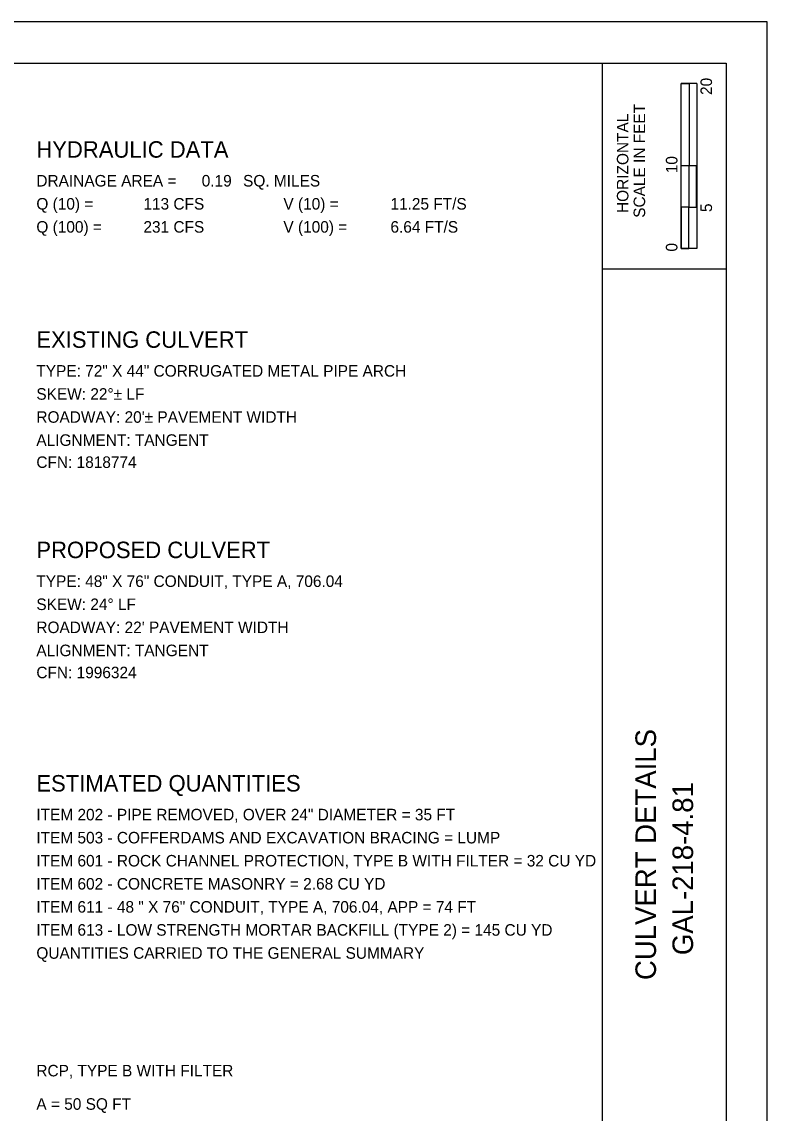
# Model space of a CAD drawing. Extents: x 0 to 2700, y -8 to 220.
# Drawn here: x 249.5 to 340, y 87.5 to 220 of the extents above; entities that cross this region are included whole.
import ezdxf

# ---------------------------------------------------------------- set-up
doc = ezdxf.new("R2010")
doc.units = 0
for name, color, linetype in [('DR_X_Culvert', 7, 'Continuous'), ('MT_P_Work_Area', 7, 'Continuous'), ('PF_X_Ground_Line', 7, 'Continuous'), ('XS_X_Pavt', 7, 'Continuous')]:
    doc.layers.add(name, color=color, linetype=linetype)

msp = doc.modelspace()

# ---------------------------------------------------------------- linework, layer by layer
at = {"layer": 'DR_X_Culvert'}
for p, q in [((329.57, 192.5), (329.57, 212.5)), ((331.44, 212.5), (329.57, 212.5)), ((329.57, 202.5), (329.57, 212.5)), ((329.57, 212.5), (330.5, 212.5)), ((330.5, 212.5), (330.51, 212.5)), ((330.51, 212.5), (330.51, 202.5)), ((331.44, 212.5), (331.44, 192.5)), ((330.51, 202.5), (329.57, 202.5)), ((331.43, 202.5), (330.5, 202.5)), ((330.5, 202.5), (330.5, 197.5)), ((331.43, 197.5), (331.43, 202.5)), ((330.5, 197.5), (329.57, 197.5)), ((329.57, 197.5), (329.57, 192.5)), ((330.5, 192.5), (330.5, 197.5)), ((330.5, 197.5), (331.43, 197.5)), ((331.44, 192.5), (329.57, 192.5)), ((329.57, 192.5), (330.5, 192.5))]:
    msp.add_line(p, q, dxfattribs=at)
at = {"layer": 'PF_X_Ground_Line'}
msp.add_lwpolyline([(0, 0), (340, 0), (340, 220), (0, 220)], close=True, dxfattribs=at)
at = {"layer": 'XS_X_Pavt'}
for p, q in [((320, 5), (320, 215)), ((320, 190), (335, 190))]:
    msp.add_line(p, q, dxfattribs=at)
msp.add_lwpolyline([(15, 215), (335, 215), (335, 5), (15, 5)], close=True, dxfattribs=at)

# ---------------------------------------------------------------- texts
at = {"layer": 'DR_X_Culvert'}
for s, height, p in [('20', 1.4, (333.3, 211.12)), ('SCALE IN FEET', 1.4, (325.18, 196.21)), ('HORIZONTAL', 1.4, (323.15, 196.79)), ('10', 1.4, (329.1, 201.62)), ('5', 1.4, (333.3, 196.91)), ('0', 1.4, (329.1, 192.11)), ('CULVERT DETAILS', 2.5, (326.5, 103.69)), ('GAL-218-4.81', 2.5, (331, 106.71))]:
    msp.add_text(s, height=height, rotation=90, dxfattribs=at).set_placement(p)
for s, height, p in [('HYDRAULIC DATA', 2, (251.25, 203.51)), ('DRAINAGE AREA =', 1.4, (251.25, 200.01)), ('0.19', 1.4, (271.33, 200.01)), ('SQ. MILES', 1.4, (276.35, 200.01)), ('Q (10) =', 1.4, (251.25, 197.21)), ('113 CFS', 1.4, (264.25, 197.21)), ('V (10) =', 1.4, (281.25, 197.21)), ('11.25 FT/S', 1.4, (294.25, 197.21)), ('Q (100) =', 1.4, (251.25, 194.41)), ('231 CFS', 1.4, (264.25, 194.41)), ('V (100) =', 1.4, (281.25, 194.41)), ('6.64 FT/S', 1.4, (294.25, 194.41)), ('EXISTING CULVERT', 2, (251.25, 180.43)), ('TYPE: 72" X 44" CORRUGATED METAL PIPE ARCH', 1.4, (251.25, 176.93)), ('SKEW: 22°± LF', 1.4, (251.25, 174.13)), ("ROADWAY: 20'± PAVEMENT WIDTH", 1.4, (251.25, 171.33)), ('ALIGNMENT: TANGENT', 1.4, (251.25, 168.53)), ('CFN: 1818774', 1.4, (251.25, 165.85)), ('PROPOSED CULVERT', 2, (251.25, 154.9)), ('TYPE: 48" X 76" CONDUIT, TYPE A, 706.04', 1.4, (251.25, 151.4)), ('SKEW: 24° LF', 1.4, (251.25, 148.6)), ("ROADWAY: 22' PAVEMENT WIDTH", 1.4, (251.25, 145.8)), ('ALIGNMENT: TANGENT', 1.4, (251.25, 143)), ('CFN: 1996324', 1.4, (251.25, 140.32)), ('ESTIMATED QUANTITIES', 2, (251.25, 126.57)), ('ITEM 202 - PIPE REMOVED, OVER 24" DIAMETER = 35 FT', 1.4, (251.25, 123.07)), ('ITEM 503 - COFFERDAMS AND EXCAVATION BRACING = LUMP', 1.4, (251.25, 120.27)), ('ITEM 601 - ROCK CHANNEL PROTECTION, TYPE B WITH FILTER = 32 CU YD', 1.4, (251.25, 117.47)), ('ITEM 602 - CONCRETE MASONRY = 2.68 CU YD', 1.4, (251.25, 114.67)), ('ITEM 611 - 48 " X 76" CONDUIT, TYPE A, 706.04, APP = 74 FT', 1.4, (251.25, 111.87)), ('ITEM 613 - LOW STRENGTH MORTAR BACKFILL (TYPE 2) = 145 CU YD', 1.4, (251.25, 109.07)), ('QUANTITIES CARRIED TO THE GENERAL SUMMARY', 1.4, (251.25, 106.27))]:
    msp.add_text(s, height=height, dxfattribs=at).set_placement(p)
at = {"layer": 'MT_P_Work_Area'}
for s, p in [('RCP, TYPE B WITH FILTER', (251.25, 91.99)), ('A = 50 SQ FT', (251.25, 87.94))]:
    msp.add_text(s, height=1.4, dxfattribs=at).set_placement(p)

doc.saveas('drawing.dxf')
